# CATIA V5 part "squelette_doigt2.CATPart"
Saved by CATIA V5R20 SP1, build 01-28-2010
Part number: squelette_doigt2
Publications: "Droite.1", "Droite.2", "Droite.3", "Plan.2"
Bounding box of the stored display mesh (mm): x -20 to 20, y 96.486 to 123.073, z -98.244 to -76.825
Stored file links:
  C:\Users\Fox\Desktop\IAO Projet\A RENDRE\Sauvegarde IFMA\squelette_doigt2.CATPart
  C:\Users\Fox\Desktop\IAO Projet\A RENDRE\Sauvegarde IFMA\squelette.CATProduct
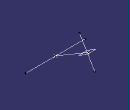
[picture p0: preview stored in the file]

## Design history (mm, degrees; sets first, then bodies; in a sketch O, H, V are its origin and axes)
Set1
  Line1: type PtPt, FirstPoint Point1, SecondPoint Point2
  Line2: type Normal, RefPoint Point1, RefSkin Plane2, Start -20, End 20
  Line3: type Angle, RefPoint Point2, Curve Line1, Support Plane2, Start -10, End 10, Angle 90
  Plane1: type Normal, Curve Line3, RefPoint Point2
Set2
  Point1: linked copy from another document
  Point2: linked copy from another document
  Plane2: linked copy from another document
Body1 (main body)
